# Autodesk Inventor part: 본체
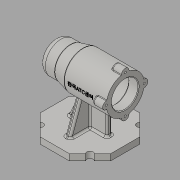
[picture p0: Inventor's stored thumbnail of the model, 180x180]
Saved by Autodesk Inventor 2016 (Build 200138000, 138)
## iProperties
Created: 2019-12
Part Number: 본체
Material: 일반
Document SubType Name: 판금
Designer: Administrator
Density: 1 g/cm^3
Appearance: 기본값
Sheet Metal Rule: 기본값
Author: Administrator
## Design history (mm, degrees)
sketch "스케치2"
  geometry: L1 (56, 0)-(-56, 0); L2 (-56, 0)-(-56, 30); L3 (-56, 30)-(11, 30); L4 (56, 0)-(56, 25); L5 (56, 25)-(31, 25); L6 (31, 25)-(11, 30); 2 further points
  constraints: 12 end point, 2 coincident, 2 perpendicular, 2 vertical, 1 horizontal, 1 midpoint
  dimensions: "d5" = 112 distance of L1.start L1.end; "d6" = 30 distance of L1.end L2.end; "d7" = 67 distance of L2.end L3.end; "d8" = 25 distance of L1.start L4.end; "d9" = 25 distance of L4.end L5.end
revolve "회전1" sketch "스케치2" stored, may be unused: angle "d10" = 180 deg
sketch "스케치3"
  geometry: C1 r 6 at (-30, 0); 2 further points
  constraints: 2 horizontal alignment, 1 centre point, 1 other
  dimensions: "d11" = 12 diameter of C1
extrude "돌출1" join sketch "스케치3" distance "d12" = 16; taper "d13" = 0 deg
hole "구멍1" diameter "d19" = 3.242; stored, may be unused: countersink angle "d23" = 90 deg, drill point angle "d25" = 118 deg; dims "d17" = 10, "d18" = 10, "d20" = 8, "d21" = 4, "d22" = 2, "d24" = 11
node "작업 평면1"
sketch "스케치4"
  geometry: L1 (-56, -6)-(-56, 6) reference; L2 (-56, 0)-(-56, 21); L3 (-56, 21)-(-41, 21); L4 (-41, 21)-(-41, 24); L5 (-41, 24)-(13, 24); L6 (13, 24)-(13, 21); L7 (13, 21)-(25, 21); L8 (25, 21)-(25, 17.5); L9 (25, 17.5)-(43, 17.5); L10 (43, 17.5)-(43, 16); L11 (43, 16)-(47, 16); L12 (47, 16)-(47, 10.5); L13 (47, 10.5)-(50, 10.5); L14 (50, 10.5)-(50, 0); L15 (50, 0)-(-56, 0); 3 further points
  constraints: 28 end point, 9 perpendicular, 2 point on line, 2 vertical, 1 collinear, 1 midpoint
  dimensions: "d30" = 21 distance of L2.start L2.end; "d31" = 15 distance of L2.end L3.end; "d32" = 3 distance of L3.end L4.end; "d33" = 54 distance of L4.end L5.end; "d34" = 3 distance of L5.end L6.end; "d35" = 12 distance of L6.end L7.end; "d36" = 3.5 distance of L7.end L8.end; "d37" = 18 distance of L8.end L9.end; "d38" = 1.5 distance of L9.end L10.end; "d39" = 4 distance of L10.end L11.end; "d40" = 5.5 distance of L11.end L12.end; "d41" = 3 distance of L12.end L13.end
revolve "회전2" sketch "스케치4" stored, may be unused: angle "d42" = 90 deg
chamfer "모따기1" distance "d44" = 1; stored, may be unused: second distance "d45" = 2, angle "d46" = 45 deg
fillet "모깎기1" dims "d47" = 3
fillet "모깎기2" dims "d48" = 3
fillet "모깎기3" dims "d49" = 0.3
fillet "모깎기4" dims "d51" = 10
node "작업 평면4"
sketch "스케치7"
  geometry: L1 (56, -23.196)-(23.196, -56); L2 (23.196, -56)-(-23.196, -56); L3 (-23.196, -56)-(-56, -23.196); L4 (-56, -23.196)-(-56, 23.196); L5 (-56, 23.196)-(-23.196, 56); L6 (-23.196, 56)-(23.196, 56); L7 (23.196, 56)-(56, 23.196); L8 (56, 23.196)-(56, -23.196); 3 further points
  constraints: 16 end point, 1 coincident, 1 horizontal alignment, 1 midpoint, 17 other
  dimensions: "d53" = 56 distance from line of L8 point (0, 0)
extrude "돌출2" join sketch "스케치7" distance "d54" = 10; taper "d55" = 0 deg
sketch "스케치8"
  geometry: L1 (56, -23.196)-(23.196, -56) reference; L2 (0, 0)-(-49.206, -49.206); L3 (0, 0)-(0, -68.274); L4 (0, 0)-(51.576, -51.576); C1 r 56 at (0, 0); C2 r 5 at (39.598, -39.598); 1 further point
  constraints: 6 end point, 2 centre point, 1 coincident, 1 midpoint, 1 vertical
  dimensions: "d56" = 112 diameter of C1; "d57" = 10 diameter of C2; "d58" = 45 deg angle of L2 L3; "d59" = 45 deg angle of L3 L4
extrude "돌출3" cut sketch "스케치8" distance "d60" = 10; taper "d61" = 0 deg
sketch "스케치9"
  geometry: L1 (-56, -23.196)-(-23.196, -56) reference; L2 (-23.196, 56)-(-56, 23.196) reference; L3 (56, 23.196)-(23.196, 56) reference; C1 r 5 at (-39.598, -39.598); C2 r 5 at (-39.598, 39.598); C3 r 5 at (39.598, 39.598); 1 further point
  constraints: 3 centre point, 3 midpoint
  dimensions: "d62" = 10 diameter of C1; "d63" = 10 diameter of C2; "d64" = 10 diameter of C3
extrude "돌출4" cut sketch "스케치9" distance "d65" = 10; taper "d66" = 0 deg
node "작업 평면5"
fillet "모깎기10" dims "d109" = 3
fillet "모깎기11" dims "d110" = 1
node "작업 평면8"
sketch "스케치14"
  geometry: L1 (56, 29.226)-(56, 6.771) reference; 2 further points
  constraints: 1 horizontal alignment, 1 other
  dimensions: "d112" = 41 distance from line of point (15, 0) L1
feature "엠보싱1" sketch "스케치14" dims "d5" = 112, "d6" = 30, "d7" = 67, "d8" = 25, "d9" = 25, "d113" = 0.5, "d114" = 0
node "작업 평면9"
node "작업 평면13"
fillet "모깎기14" dims "d153" = 3
node "작업 평면20"
sketch "스케치32"
  geometry: L1 (-36.062, -70)-(-23.196, -70) reference; L2 (-31, -70)-(-31, -29.698); L3 (-56, -80)-(-56, -70) reference; L4 (23.196, -70)-(36.062, -70) reference; L5 (31, -70)-(12.207, -29.698); L6 (11.358, -29.91)-(30.642, -25.09) reference; L7 (56, -80)-(56, -70) reference; L8 (43.134, -70)-(56, -70) reference; L9 (12.207, -29.698)-(-31, -29.698); L10 (31, -70)-(-31, -70); 1 further point
  constraints: 8 end point, 2 point on line, 1 collinear, 1 perpendicular, 1 vertical
  dimensions: "d196" = 25 distance between parallel lines of L2 L3; "d197" = 25 distance from line of L5.start L7; "d198" = 115 deg angle of L8 L5
extrude "돌출10" join sketch "스케치32" distance "d199" = 4; taper "d201" = 0 deg; dims "d200" = 4, "d202" = 0
node "작업 평면21"
sketch "스케치33"
  geometry: L1 (36.062, -70)-(23.196, -70) reference; L2 (36, -70)-(19.318, -24.166); L3 (56, -80)-(56, -70) reference; L4 (56, -70)-(43.134, -70) reference; 1 further point
  constraints: 2 end point, 1 point on line
  dimensions: "d204" = 20 distance from line of L2.start L3; "d205" = 110 deg angle of L2 L4
feature "리브4" sketch "스케치33" dims "d206" = 1, "d207" = 8, "d208" = 0, "d209" = 0, "d210" = 1, "d211" = 1
fillet "모깎기15" dims "d212" = 3
fillet "모깎기16" dims "d213" = 3
node "솔리드1"
pattern_circular "원형 패턴1" dims angle "d15" = 360 deg
pattern_circular "원형 패턴2" dims angle "d27" = 360 deg
mirror "대칭4"
other parameters: "d29" = 0, "d67" = 0, "d115" = 0, "d145" = 0, "K계수" = 4.4, "BendRadius" = 0.5 (derived), "BendReliefWidth" = 0.5 (derived), "BendReliefDepth" = 0.25 (derived), "CornerReliefSize" = 2 (derived), "SeamGap" = 0.01, "MinimumRemnant" = 1 (derived), "TransitionRadius" = 0.5 (= BendRadius), "d195" = 0, "d203" = 0
